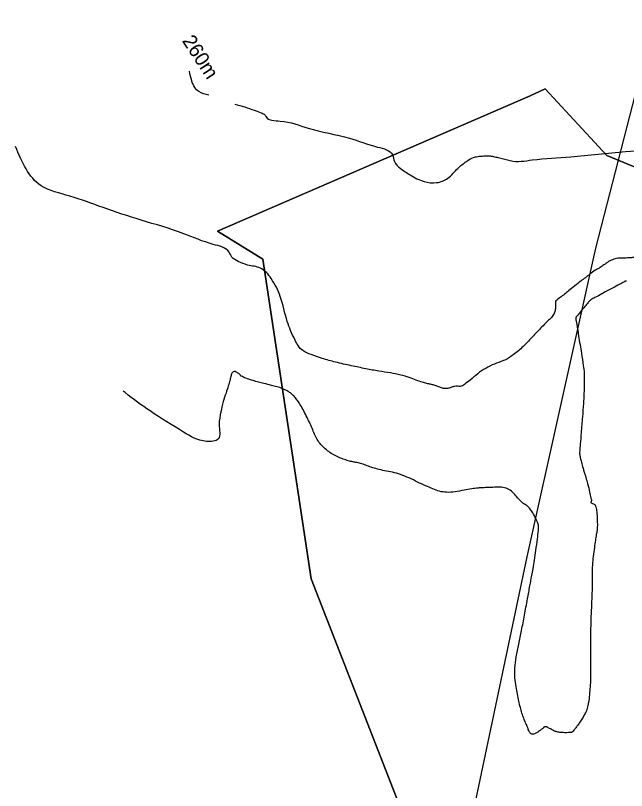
# Model space of a CAD drawing. Extents: x -478495 to -472450, y -1118050 to -1113745.
# Drawn here: x -475265.5 to -475188, y -1116412.5 to -1116314.2 of the extents above; entities that cross this region are included whole.
import ezdxf

# ---------------------------------------------------------------- set-up
doc = ezdxf.new("R2010")
doc.units = 0
for name, color, linetype in [('el vedeni_NN', 7, 'Continuous'), ('ObPÚ', 7, 'Continuous'), ('Vrstevnice_hlavni', 7, 'Continuous'), ('Vrstevnice_popis', 7, 'Continuous'), ('Vrstevnice_vedlejsi', 7, 'Continuous')]:
    doc.layers.add(name, color=color, linetype=linetype)

msp = doc.modelspace()

# ---------------------------------------------------------------- linework, layer by layer
at = {"layer": 'el vedeni_NN'}
msp.add_lwpolyline([(-475215.653, -1116453.785), (-475209.515, -1116425.189), (-475200.612, -1116382.866), (-475191.904, -1116343.75), (-475181.881, -1116304.784)], dxfattribs=at)
at = {"layer": 'ObPÚ'}
for p, q in [((-475239.871, -1116341.562), (-475200.24, -1116324.431)), ((-475200.24, -1116324.431), (-475239.871, -1116341.562)), ((-475200.24, -1116324.431), (-475198.322, -1116323.536)), ((-475198.322, -1116323.536), (-475200.24, -1116324.431)), ((-475198.322, -1116323.536), (-475190.524, -1116331.974)), ((-475190.524, -1116331.974), (-475198.322, -1116323.536)), ((-475190.524, -1116331.974), (-475181.958, -1116335.553)), ((-475181.958, -1116335.553), (-475190.524, -1116331.974)), ((-475234.118, -1116345.141), (-475239.871, -1116341.562)), ((-475239.871, -1116341.562), (-475234.118, -1116345.141)), ((-475227.981, -1116385.667), (-475234.118, -1116345.141)), ((-475234.118, -1116345.141), (-475227.981, -1116385.667)), ((-475215.325, -1116418.139), (-475227.981, -1116385.667)), ((-475227.981, -1116385.667), (-475215.325, -1116418.139))]:
    msp.add_line(p, q, dxfattribs=at)
at = {"layer": 'Vrstevnice_hlavni'}
for points in [[(-475240.975, -1116324.335), (-475242.24, -1116323.875), (-475242.75, -1116323.343), (-475243.137, -1116322.506), (-475243.415, -1116321.305)], [(-475237.687, -1116325.457), (-475235.201, -1116326.249), (-475234.334, -1116326.581), (-475233.844, -1116326.849), (-475233.73, -1116327.052), (-475231.91, -1116327.609), (-475228.384, -1116328.517), (-475223.153, -1116329.779), (-475219.586, -1116330.906), (-475217.681, -1116331.898), (-475217.44, -1116332.755), (-475216.694, -1116333.605), (-475215.441, -1116334.448), (-475213.683, -1116335.283), (-475212.092, -1116335.422), (-475210.667, -1116334.864), (-475209.409, -1116333.609), (-475208.319, -1116332.727), (-475207.397, -1116332.218), (-475206.642, -1116332.081), (-475205.948, -1116332.022), (-475205.314, -1116332.042), (-475204.739, -1116332.139), (-475204.122, -1116332.27), (-475203.462, -1116332.435), (-475202.76, -1116332.635), (-475199.972, -1116332.541), (-475195.097, -1116332.152), (-475188.137, -1116331.469), (-475183.035, -1116331.113), (-475179.791, -1116331.083), (-475178.406, -1116331.38), (-475177.36, -1116331.658), (-475176.654, -1116331.916), (-475176.288, -1116332.154), (-475175.662, -1116332.174), (-475174.776, -1116331.975), (-475173.631, -1116331.557), (-475172.686, -1116331.362), (-475171.941, -1116331.391), (-475171.397, -1116331.643), (-475170.862, -1116332.357), (-475170.337, -1116333.533), (-475169.822, -1116335.172), (-475169.381, -1116336.301), (-475169.015, -1116336.92), (-475168.725, -1116337.029), (-475167.953, -1116337.013), (-475166.701, -1116336.871), (-475164.969, -1116336.603), (-475163.238, -1116336.553), (-475161.509, -1116336.722), (-475159.783, -1116337.108), (-475158.522, -1116337.413), (-475157.729, -1116337.635), (-475157.401, -1116337.776), (-475157.09, -1116337.883), (-475156.795, -1116337.957), (-475156.517, -1116337.998), (-475155.978, -1116338.488), (-475155.178, -1116339.429), (-475154.117, -1116340.82), (-475152.888, -1116341.664), (-475151.489, -1116341.961), (-475149.92, -1116341.711), (-475148.805, -1116341.537), (-475148.141, -1116341.439), (-475147.93, -1116341.416), (-475147.518, -1116341.551), (-475146.905, -1116341.845), (-475146.091, -1116342.298), (-475145.239, -1116342.772), (-475144.347, -1116343.269), (-475143.416, -1116343.787), (-475142.747, -1116344.148), (-475142.34, -1116344.352), (-475142.195, -1116344.4), (-475141.824, -1116344.514), (-475141.227, -1116344.693), (-475140.403, -1116344.939), (-475139.648, -1116345.093), (-475138.96, -1116345.154), (-475138.341, -1116345.124), (-475137.645, -1116345.157), (-475136.873, -1116345.252), (-475136.023, -1116345.411), (-475135.095, -1116345.637), (-475134.087, -1116345.929), (-475132.999, -1116346.289), (-475132.178, -1116346.581), (-475131.622, -1116346.805), (-475131.332, -1116346.962), (-475131.076, -1116347.169), (-475130.854, -1116347.427), (-475130.666, -1116347.736), (-475129.952, -1116348.756), (-475128.712, -1116350.487)]]:
    msp.add_spline(points, degree=3, dxfattribs=at)
at = {"layer": 'Vrstevnice_vedlejsi'}
for points in [[(-475158.731, -1116348.111), (-475159.722, -1116347.73), (-475160.912, -1116347.451), (-475162.3, -1116347.275), (-475163.886, -1116347.201), (-475165.382, -1116347.074), (-475166.785, -1116346.895), (-475168.098, -1116346.663), (-475169.415, -1116346.436), (-475170.735, -1116346.214), (-475172.06, -1116345.996), (-475173.309, -1116345.754), (-475174.481, -1116345.488), (-475175.577, -1116345.197), (-475176.528, -1116344.968), (-475177.333, -1116344.801), (-475177.993, -1116344.696), (-475178.759, -1116344.641), (-475179.63, -1116344.636), (-475180.606, -1116344.682), (-475181.738, -1116344.715), (-475183.026, -1116344.736), (-475184.47, -1116344.745), (-475185.607, -1116344.776), (-475186.437, -1116344.827), (-475186.96, -1116344.9), (-475187.554, -1116344.953), (-475188.219, -1116344.986), (-475188.954, -1116344.999), (-475189.644, -1116345.147), (-475190.288, -1116345.431), (-475190.886, -1116345.85), (-475191.368, -1116346.174), (-475191.735, -1116346.403), (-475191.986, -1116346.536), (-475192.676, -1116347.039), (-475193.804, -1116347.91), (-475195.37, -1116349.15), (-475196.425, -1116349.99), (-475196.969, -1116350.431), (-475197.002, -1116350.471), (-475197.026, -1116350.667), (-475197.041, -1116351.02), (-475197.047, -1116351.53), (-475197.212, -1116352.028), (-475197.537, -1116352.515), (-475198.022, -1116352.991), (-475198.781, -1116353.764), (-475199.814, -1116354.835), (-475201.12, -1116356.204), (-475202.383, -1116357.259), (-475203.601, -1116357.999), (-475204.774, -1116358.424), (-475205.87, -1116358.977), (-475206.887, -1116359.66), (-475207.826, -1116360.471), (-475208.565, -1116361.005), (-475209.105, -1116361.262), (-475209.445, -1116361.241), (-475209.807, -1116361.275), (-475210.191, -1116361.363), (-475210.596, -1116361.506), (-475211.022, -1116361.538), (-475211.468, -1116361.459), (-475211.935, -1116361.269), (-475212.4, -1116361.113), (-475212.862, -1116360.991), (-475213.322, -1116360.903), (-475213.925, -1116360.731), (-475214.671, -1116360.473), (-475215.56, -1116360.132), (-475216.647, -1116359.827), (-475217.932, -1116359.56), (-475219.414, -1116359.329), (-475221.073, -1116359.024), (-475222.906, -1116358.645), (-475224.916, -1116358.191), (-475226.611, -1116357.719), (-475227.992, -1116357.23), (-475229.059, -1116356.723), (-475230.069, -1116355.322), (-475231.023, -1116353.029), (-475231.919, -1116349.842), (-475233.058, -1116347.587), (-475234.439, -1116346.264), (-475236.062, -1116345.872), (-475237.26, -1116345.405), (-475238.033, -1116344.861), (-475238.381, -1116344.242), (-475240.418, -1116343.253), (-475244.143, -1116341.897), (-475249.556, -1116340.172), (-475254.377, -1116338.582), (-475258.605, -1116337.127), (-475262.24, -1116335.808), (-475265.477, -1116330.842)], [(-475188.022, -1116347.916), (-475188.118, -1116347.918), (-475188.207, -1116347.937), (-475188.291, -1116347.974), (-475188.368, -1116348.028), (-475188.867, -1116348.302), (-475189.787, -1116348.796), (-475191.128, -1116349.509), (-475192.049, -1116350.005), (-475192.55, -1116350.286), (-475192.631, -1116350.35), (-475192.879, -1116350.629), (-475193.293, -1116351.123), (-475193.874, -1116351.832), (-475194.261, -1116352.309), (-475194.455, -1116352.554), (-475194.455, -1116352.568), (-475194.455, -1116352.589), (-475194.453, -1116352.616), (-475194.451, -1116352.65), (-475194.331, -1116353.402), (-475194.093, -1116354.873), (-475193.737, -1116357.062), (-475193.497, -1116358.62), (-475193.374, -1116359.547), (-475193.367, -1116359.843), (-475193.372, -1116360.37), (-475193.389, -1116361.128), (-475193.417, -1116362.116), (-475193.49, -1116363.448), (-475193.608, -1116365.123), (-475193.772, -1116367.141), (-475193.887, -1116368.581), (-475193.953, -1116369.442), (-475193.97, -1116369.725), (-475193.915, -1116370.149), (-475193.789, -1116370.715), (-475193.592, -1116371.423), (-475193.46, -1116371.896), (-475193.394, -1116372.135), (-475193.393, -1116372.139), (-475193.375, -1116372.184), (-475193.34, -1116372.269), (-475193.288, -1116372.395), (-475193.163, -1116372.836), (-475192.966, -1116373.594), (-475192.696, -1116374.668), (-475192.535, -1116375.417), (-475192.484, -1116375.841), (-475192.542, -1116375.94), (-475192.497, -1116376.03), (-475192.351, -1116376.11), (-475192.102, -1116376.181), (-475191.916, -1116376.537), (-475191.791, -1116377.179), (-475191.729, -1116378.108), (-475191.717, -1116378.896), (-475191.757, -1116379.544), (-475191.847, -1116380.052), (-475191.959, -1116380.768), (-475192.094, -1116381.693), (-475192.252, -1116382.826), (-475192.352, -1116383.918), (-475192.394, -1116384.97), (-475192.379, -1116385.98), (-475192.394, -1116387.165), (-475192.438, -1116388.525), (-475192.511, -1116390.058), (-475192.559, -1116391.582), (-475192.582, -1116393.096), (-475192.579, -1116394.6), (-475192.576, -1116395.902), (-475192.573, -1116397.002), (-475192.569, -1116397.901), (-475192.601, -1116398.849), (-475192.669, -1116399.846), (-475192.774, -1116400.892), (-475192.918, -1116401.742), (-475193.101, -1116402.397), (-475193.325, -1116402.857), (-475193.6, -1116403.337), (-475193.927, -1116403.838), (-475194.305, -1116404.359), (-475194.59, -1116404.741), (-475194.781, -1116404.983), (-475194.879, -1116405.086), (-475195.149, -1116405.151), (-475195.592, -1116405.177), (-475196.208, -1116405.165), (-475196.732, -1116405.095), (-475197.166, -1116404.967), (-475197.509, -1116404.782), (-475197.765, -1116404.64), (-475197.936, -1116404.543), (-475198.021, -1116404.489), (-475198.122, -1116404.455), (-475198.237, -1116404.44)], [(-475236.858, -1116359.958), (-475237.06, -1116359.737), (-475237.278, -1116359.565), (-475237.512, -1116359.444), (-475237.762, -1116359.371), (-475237.974, -1116359.516), (-475238.149, -1116359.877), (-475238.285, -1116360.455), (-475238.498, -1116361.198), (-475238.789, -1116362.107), (-475239.157, -1116363.182), (-475239.445, -1116364.507), (-475239.652, -1116366.083), (-475239.779, -1116367.911), (-475241.284, -1116368.236), (-475244.166, -1116367.06), (-475248.426, -1116364.381), (-475251.559, -1116362.054), (-475251.817, -1116361.843)], [(-475198.237, -1116404.44), (-475198.369, -1116404.444), (-475198.465, -1116404.465), (-475198.525, -1116404.502), (-475198.551, -1116404.557), (-475198.698, -1116404.685), (-475198.967, -1116404.889), (-475199.358, -1116405.166), (-475199.676, -1116405.332), (-475199.92, -1116405.387), (-475200.091, -1116405.331), (-475200.239, -1116405.206), (-475200.365, -1116405.014), (-475200.47, -1116404.754), (-475200.62, -1116404.388), (-475200.815, -1116403.918), (-475201.056, -1116403.343), (-475201.277, -1116402.696), (-475201.478, -1116401.977), (-475201.659, -1116401.185), (-475201.833, -1116400.299), (-475202, -1116399.317), (-475202.161, -1116398.241), (-475202.159, -1116396.99), (-475201.994, -1116395.565), (-475201.667, -1116393.964), (-475201.321, -1116392.206), (-475200.957, -1116390.29), (-475200.574, -1116388.215), (-475200.266, -1116386.54), (-475200.032, -1116385.263), (-475199.872, -1116384.386), (-475199.697, -1116383.316), (-475199.508, -1116382.054), (-475199.304, -1116380.6), (-475199.196, -1116379.537), (-475199.184, -1116378.867), (-475199.268, -1116378.587), (-475199.428, -1116378.211), (-475199.666, -1116377.739), (-475199.98, -1116377.171), (-475200.314, -1116376.716), (-475200.669, -1116376.373), (-475201.045, -1116376.143), (-475201.47, -1116375.781), (-475201.943, -1116375.287), (-475202.466, -1116374.661), (-475203.109, -1116374.248), (-475203.873, -1116374.048), (-475204.757, -1116374.062), (-475205.547, -1116374.084), (-475206.243, -1116374.116), (-475206.845, -1116374.156), (-475207.632, -1116374.258), (-475208.603, -1116374.422), (-475209.76, -1116374.647), (-475210.807, -1116374.692), (-475211.745, -1116374.559), (-475212.573, -1116374.245), (-475213.49, -1116373.859), (-475214.496, -1116373.402), (-475215.59, -1116372.872), (-475216.653, -1116372.454), (-475217.687, -1116372.15), (-475218.691, -1116371.958), (-475219.591, -1116371.744), (-475220.388, -1116371.509), (-475221.082, -1116371.252), (-475221.724, -1116371.049), (-475222.316, -1116370.899), (-475222.856, -1116370.804), (-475223.449, -1116370.644), (-475224.095, -1116370.419), (-475224.793, -1116370.13), (-475225.45, -1116369.757), (-475226.068, -1116369.3), (-475226.644, -1116368.76), (-475227.125, -1116368.157), (-475227.509, -1116367.492), (-475227.796, -1116366.764), (-475228.129, -1116365.999), (-475228.509, -1116365.198), (-475228.934, -1116364.361), (-475229.337, -1116363.651), (-475229.719, -1116363.07), (-475230.079, -1116362.617), (-475230.45, -1116362.243), (-475230.83, -1116361.948), (-475231.221, -1116361.732), (-475231.601, -1116361.557), (-475231.97, -1116361.423), (-475232.328, -1116361.331), (-475233.007, -1116361.152), (-475234.009, -1116360.885), (-475235.333, -1116360.532), (-475236.282, -1116360.223), (-475236.858, -1116359.958)]]:
    msp.add_spline(points, degree=3, dxfattribs=at)

# ---------------------------------------------------------------- texts
at = {"layer": 'Vrstevnice_popis'}
msp.add_text(' 260m ', height=1.8, rotation=303.2134, dxfattribs=at).set_placement((-475244.785, -1116316.873))

doc.saveas('drawing.dxf')
